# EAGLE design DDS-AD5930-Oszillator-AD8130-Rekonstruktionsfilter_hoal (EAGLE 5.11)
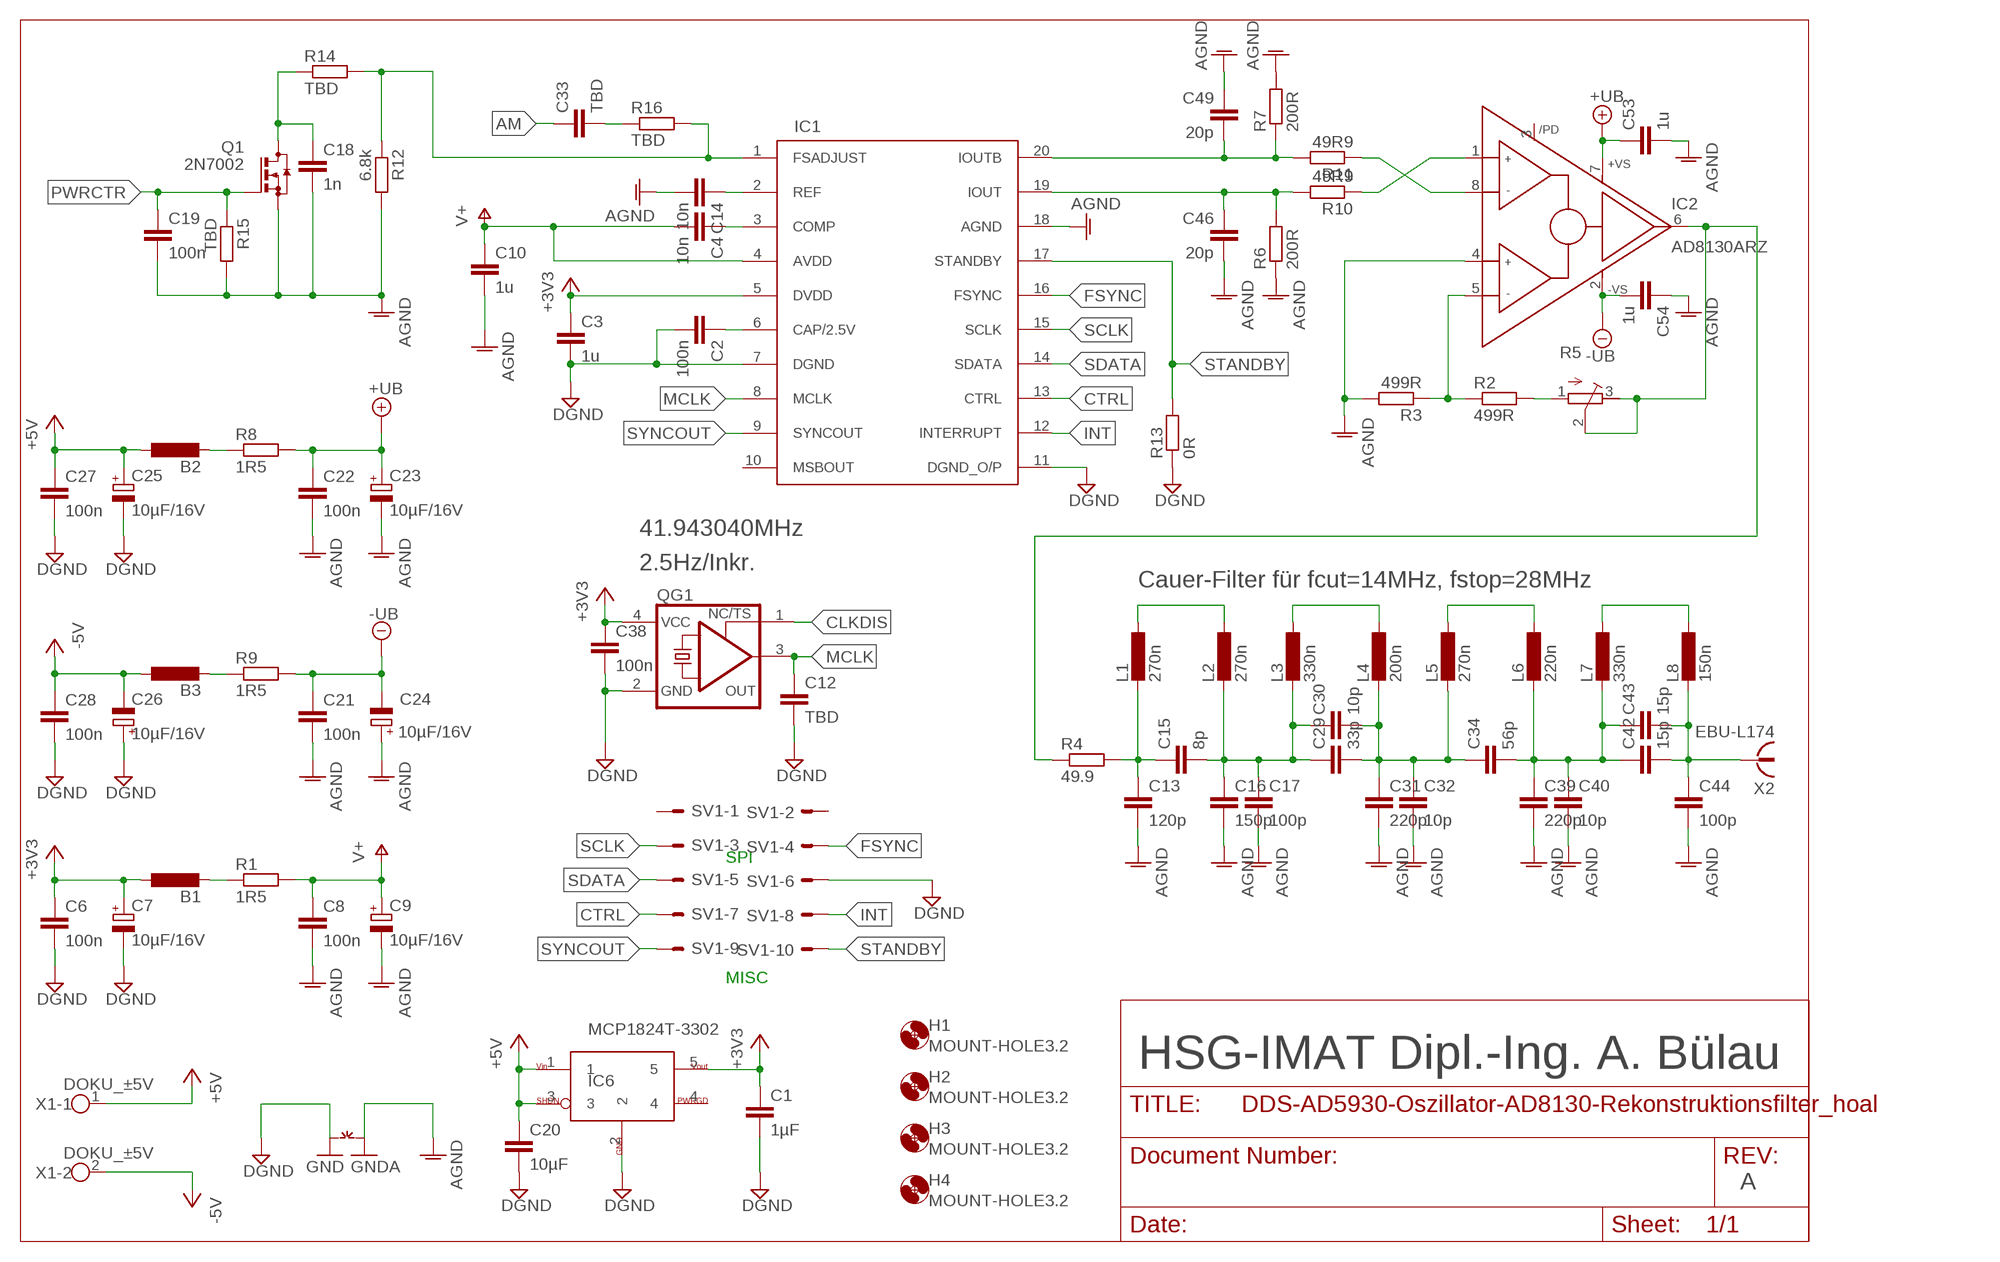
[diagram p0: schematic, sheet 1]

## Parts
B1  FERRITE-BEAD-SMD1206  [L1206]
B2  FERRITE-BEAD-SMD1206  [L1206]
B3  FERRITE-BEAD-SMD1206  [L1206]
C1  1µF  C-EUC0603  [C0603]
C2  100n  C-EUC0603  [C0603]
C3  1u  C-EUC0603  [C0603]
C4  10n  C-EUC0603  [C0603]
C6  100n  C-EUC0603  [C0603]
C7  10µF/16V  CPOL-EUSMCB  [SMC_B]
C8  100n  C-EUC0603  [C0603]
C9  10µF/16V  CPOL-EUSMCB  [SMC_B]
C10  1u  C-EUC0603  [C0603]
C12  TBD  C-EUC0603  [C0603]
C13  120p  C-EUC0805  [C0805]
C14  10n  C-EUC0603  [C0603]
C15  8p  C-EUC0805  [C0805]
C16  150p  C-EUC0805  [C0805]
C17  100p  C-EUC0805  [C0805]
C18  1n  C-EUC0603  [C0603]
C19  100n  C-EUC0603  [C0603]
C20  10µF  C-EUC1206  [C1206]
C21  100n  C-EUC0603  [C0603]
C22  100n  C-EUC0603  [C0603]
C23  10µF/16V  CPOL-EUSMCB  [SMC_B]
C24  10µF/16V  CPOL-EUSMCB  [SMC_B]
C25  10µF/16V  CPOL-EUSMCB  [SMC_B]
C26  10µF/16V  CPOL-EUSMCB  [SMC_B]
C27  100n  C-EUC0603  [C0603]
C28  100n  C-EUC0603  [C0603]
C29  33p  C-EUC0805  [C0805]
C30  10p  C-EUC0805  [C0805]
C31  220p  C-EUC0805  [C0805]
C32  10p  C-EUC0805  [C0805]
C33  TBD  C-EUC0603  [C0603]
C34  56p  C-EUC0805  [C0805]
C38  100n  C-EUC0603  [C0603]
C39  220p  C-EUC0805  [C0805]
C40  10p  C-EUC0805  [C0805]
C42  15p  C-EUC0805  [C0805]
C43  15p  C-EUC0805  [C0805]
C44  100p  C-EUC0805  [C0805]
C46  20p  C-EUC0603  [C0603]
C49  20p  C-EUC0603  [C0603]
C53  1u  C-EUC0603  [C0603]
C54  1u  C-EUC0603  [C0603]
H1  MOUNT-HOLE3.2  [3,2]
H2  MOUNT-HOLE3.2  [3,2]
H3  MOUNT-HOLE3.2  [3,2]
H4  MOUNT-HOLE3.2  [3,2]
IC1  AD5930  [TSSOP20]
IC2  AD8130ARZ  [SO8]
IC6  MCP1824T-3302  MCP1824T  [SOT23-5]
L1  270n  L-EUL1008  [L1008]
L2  270n  L-EUL1008  [L1008]
L3  330n  L-EUL1008  [L1008]
L4  200n  L-EUL1008  [L1008]
L5  270n  L-EUL1008  [L1008]
L6  220n  L-EUL1008  [L1008]
L7  330n  L-EUL1008  [L1008]
L8  150n  L-EUL1008  [L1008]
Q1  2N7002  BSS123  [SOT23]
QG1  XO-91  [91]
R1  1R5  R-EU_R0805  [R0805]
R2  499R  R-EU_R0603  [R0603]
R3  499R  R-EU_R0603  [R0603]
R4  49.9  R-EU_R0805  [R0805]
R5  R-TRIMM3314J  [RTRIM3314J]
R6  200R  R-EU_R0603  [R0603]
R7  200R  R-EU_R0603  [R0603]
R8  1R5  R-EU_R0805  [R0805]
R9  1R5  R-EU_R0805  [R0805]
R10  49R9  R-EU_R0603  [R0603]
R11  49R9  R-EU_R0603  [R0603]
R12  6.8k  R-EU_R0603  [R0603]
R13  0R  R-EU_R0603  [R0603]
R14  TBD  R-EU_R0603  [R0603]
R15  TBD  R-EU_R0603  [R0603]
R16  TBD  R-EU_R0603  [R0603]
SV1  ML10E  [ML10]
X1  DOKU_±5V  [DOKU_±5V]
X2  EBU-L174  [SMB_EBU-L174]
~NUDEV~1  GND-GNDAVIA  GND-GNDA  [GND-GNDA]

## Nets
+3V3: B1.1 C1.1 C3.1 C6.1 C7.+ C38.1 IC1.5(DVDD) IC6.5 QG1.4(VCC)
+5V: B2.1 C20.1 C25.+ C27.1 IC6.1 IC6.3 X1.1
+UB: C22.1 C23.+ C53.1 IC2.7(+VS) R8.2
-5V: B3.1 C26.- C28.2 X1.2
-UB: C21.2 C24.- C54.2 IC2.2(-VS) R9.2
AGND: C8.2 C9.- C10.2 C13.2 C14.2 C16.2 C17.2 C18.2 C19.2 C21.1 C22.2 C23.- C24.+ C31.2 C32.2 C39.2 C40.2 C44.2 C46.2 C49.2 C53.2 C54.1 IC1.18(AGND) IC2.4(REF) Q1.2(S) R3.2 R6.1 R7.2 R12.2 R15.2 ~NUDEV~1.GNDA
AM: C33.1
CLKDIS: QG1.1(TS)
CTRL: IC1.13(CTRL) SV1.7
DGND: C1.2 C2.2 C3.2 C6.2 C7.- C12.2 C20.2 C25.- C26.+ C27.2 C28.1 C38.2 IC1.7(DGND) IC1.11(DGND_O/P) IC6.2 QG1.2(GND) R13.1 SV1.6 ~NUDEV~1.GND
FSADJUST: IC1.1(FSADJUST) R12.1 R14.2 R16.2
FSYNC: IC1.16(FSYNC) SV1.4
INT: IC1.12(INTERRUPT) SV1.8
MCLK: C12.1 IC1.8(MCLK) QG1.3(OUT)
N$1: C13.1 C15.1 L1.2 R4.2
N$2: L1.1 L2.1
N$3: C15.2 C16.1 C17.1 C29.1 C30.1 L2.2 L3.2
N$4: C29.2 C30.2 C31.1 C32.1 C34.1 L4.2 L5.2
N$5: L3.1 L4.1
N$6: L5.1 L6.1
N$7: C33.2 R16.1
N$8: B1.2 R1.1
N$9: C2.1 IC1.6(CAP/2.5V)
N$12: C34.2 C39.1 C40.1 C42.1 C43.1 L6.2 L7.2
N$13: C4.1 IC1.3(COMP)
N$14: B2.2 R8.1
N$15: C49.1 IC1.20(IOUTB) R7.1 R11.2
N$16: L7.1 L8.1
N$17: C46.1 IC1.19(IOUT) R6.2 R10.2
N$18: B3.2 R9.1
N$19: IC2.1(IN+) R10.1
N$20: R2.2 R5.1(E)
N$22: IC2.8(IN-) R11.1
N$23: C18.1 Q1.3(D) R14.1
N$24: C14.1 IC1.2(REF)
N$26: IC2.5(FB) R2.1 R3.1
OUT: C42.2 C43.2 C44.1 L8.2 X2.1
PWRCTR: C19.1 Q1.1(G) R15.1
SCLK: IC1.15(SCLK) SV1.3
SDATA: IC1.14(SDATA) SV1.5
STANDBY: IC1.17(STANDBY) R13.2 SV1.10
SYNCOUT: IC1.9(SYNCOUT) SV1.9
V+: C4.2 C8.1 C9.+ C10.1 IC1.4(AVDD) R1.2
VRAW: IC2.6(OUT) R4.1 R5.2(S) R5.3(A)
Unconnected: IC1.10(MSBOUT) IC2.3(/PD) IC6.4 SV1.1 SV1.2

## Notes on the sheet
- 41.943040MHz
- 2.5Hz/Inkr.
- Cauer-Filter für fcut=14MHz, fstop=28MHz
- SPI
- MISC
- HSG-IMAT Dipl.-Ing. A. Bülau
- A

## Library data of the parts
B1-B3 = rcl:FERRITE-BEAD-SMD
C1-C4 C6 C8 C10 C12-C22 C27-C34 C38-C40 C42-C44 C46 C49 C53 C54 = rcl:C-EU: CAPACITOR, European symbol
C7 C9 C23-C26 = rcl:CPOL-EU: POLARIZED CAPACITOR, European symbol
H1-H4 = holes:MOUNT-HOLE: MOUNTING HOLE with drill center marker
IC1 = ad5930:AD5930
IC2 = AD8130:AD8130: Differential Receiver Amplifier
IC6 = MCP1824:MCP1824: 300mA, Low Voltage, Low Quiescent Current LDO Regulator
L1-L8 = rcl:L-EU: INDUCTOR, European symbol
Q1 = transistor-small-signal:BSS123: N-CHANNEL MOS FET
QG1 = crystal:XO-: CRYSTAL
R1-R4 R6-R16 = rcl:R-EU_: RESISTOR, European symbol
R5 = rcl:R-TRIMM: Trimm resistor
SV1 = con-ml:ML10E: HARTING
X1 = Spannungsdurchführung:DOKU_±5V
X2 = SMB-Reichelt:EBU-L174: Löt-Einbaubuchse
~NUDEV~1 = supply-dummy:GND-GNDA: Example of GND--GNDA NET-Connetor for more info read description in package

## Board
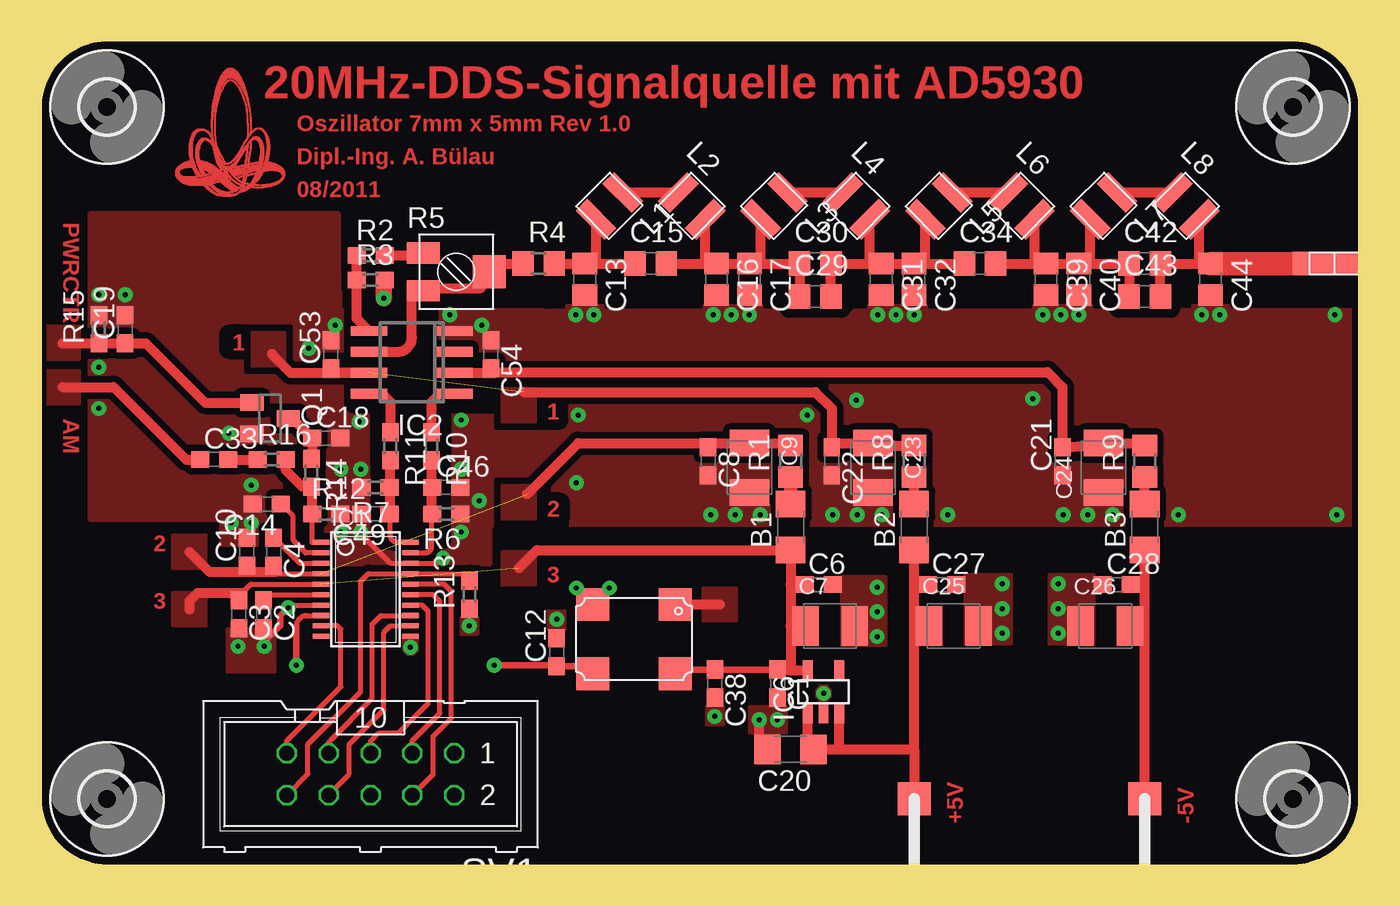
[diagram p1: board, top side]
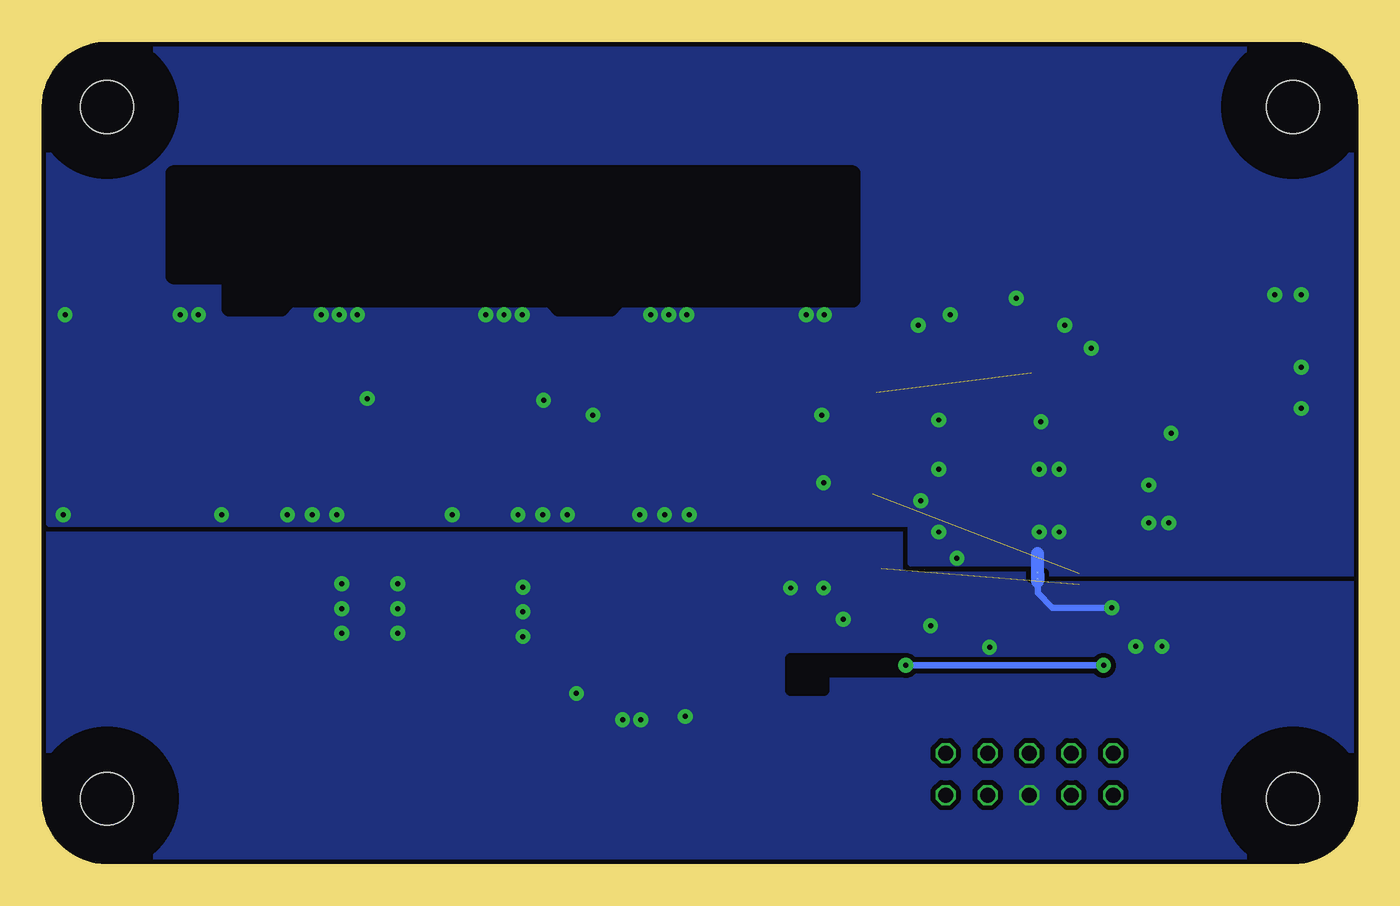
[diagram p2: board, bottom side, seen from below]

Size 80 x 50 mm. Coordinates in mm from the lower left corner, seen from the top.
Outline: 0,4 arc90 4,0 76,0 arc90 80,4 80,46 arc90 76,50 4,50 arc90 0,46 0,4
Copper layers (1*16): Top 0.035mm / dielectric 0.8mm / Bottom 0.035mm
Design rules "A. BÃ¼lau *": minimum track width 0.15mm, minimum drill 0.3mm, track to track 0.3mm, track to pad 0.15mm, pad to pad 0.15mm, via to via 0.15mm, smd to smd 0.15mm, copper to edge 0.3mm, drill to drill 0.3mm, minimum pad ring 0.15mm, minimum via ring 0.15mm, stop-mask expansion 0.3mm, vias tented up to drill 0.3mm, thermal gap 10mil
tRestrict: area 30.7,33.8 to 72,42; area 11.4,31.3 to 12.2,32.2; area 19,19.7 to 27.3,33.5; area 30.6,27 to 31.4,27.9; area 30.7,21.1 to 31.5,22; area 30.7,17.1 to 31.5,18
bRestrict: area 30.7,33.8 to 72,42; area 27.5,10.6 to 34.5,12.5
Milling: 8 lines

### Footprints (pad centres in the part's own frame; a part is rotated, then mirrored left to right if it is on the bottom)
L1206 = smd 1.6 x 1.8: 1 -1.4,0; 2 1.4,0
C0603 = smd 1.1 x 1: 1 -0.85,0; 2 0.85,0
SMC_B = smd 1.6 x 2.4: + -1.5,0; - 1.5,0
C0805 = smd 1.3 x 1.5: 1 -0.95,0; 2 0.95,0
C1206 = smd 1.6 x 1.8: 1 -1.4,0; 2 1.4,0
3,2 = hole 3.2: 0,0
TSSOP20 = smd 0.305 x 0.991: 1 -3.175,-2.718; 2 -2.54,-2.718; 3 -1.905,-2.718; 4 -1.27,-2.718; 5 -0.635,-2.718; 6 0,-2.718; 7 0.635,-2.718; 8 1.27,-2.718; 9 1.905,-2.718; 10 2.54,-2.718; 11 2.54,2.718; 12 1.905,2.718; 13 1.27,2.718; 14 0.635,2.718; 15 0,2.718; 16 -0.635,2.718; 17 -1.27,2.718; 18 -1.905,2.718; 19 -2.54,2.718; 20 -3.175,2.718
SO8 = smd 0.6 x 2.2: 1 -1.905,-2.6; 2 -0.635,-2.6; 3 0.635,-2.6; 4 1.905,-2.6; 5 1.905,2.6; 6 0.635,2.6; 7 -0.635,2.6; 8 -1.905,2.6
SOT23-5 = smd 0.6 x 1.2: 1 -0.95,-1.306; 2 0,-1.306; 3 0.95,-1.306; 4 0.95,1.306; 5 -0.95,1.306
L1008 = smd 1 x 2.5: 1 -1.15,0; 2 1.15,0
SOT23 = smd 1 x 1.4: 1 -0.95,-1.1; 2 0.95,-1.1; 3 0,1.1
91 = smd 2 x 2: 1 -2.5,-2.1; 2 2.5,-2.1; 3 2.5,2.1; 4 -2.5,2.1
R0805 = smd 1.3 x 1.5: 1 -0.95,0; 2 0.95,0
R0603 = smd 1.1 x 1: 1 -0.85,0; 2 0.85,0
RTRIM3314J = smd 1.3 x 2: 1 -1.15,-2; 3 1.15,-2 | smd 2 x 2: 2 0,2
ML10 = drill 0.914 octagon: 1 -5.08,-1.27; 2 -5.08,1.27; 3 -2.54,-1.27; 4 -2.54,1.27; 5 0,-1.27; 6 0,1.27; 7 2.54,-1.27; 8 2.54,1.27; 9 5.08,-1.27; 10 5.08,1.27
DOKU_±5V = smd 2 x 2: 1 0,-7; 2 0,7
SMB_EBU-L174 = smd 4 x 1.44: 1 -2,0
GND-GNDA = smd 0.1 x 0.1: GND 0.25,0; GNDA -0.15,0

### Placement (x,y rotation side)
B1  45.5,20.5 90 top
B2  53,20.5 90 top
B3  67,20.5 90 top
C1  44.7,11 270 top
C2  13.5,15.2 270 top
C3  12,15.2 270 top
C4  14.1,19 270 top
C6  47.2,17 0 top
C7  47.9,14.5 0 top
C8  40.5,24.5 270 top
C9  43,24.1 270 top
C10  12.5,19 90 top
C12  31.3,12.9 90 top
C13  33,35.55 270 top
C14  13.7,21.9 180 top
C15  37,36.5 0 top
C16  41,35.55 270 top
C17  43,35.55 270 top
C18  17.3,25.9 0 top
C19  5.1,32.5 90 top
C20  45.5,7 180 top
C21  62,24.5 90 top
C22  48,24.5 270 top
C23  50.5,24.1 270 top
C24  64.5,24.1 90 top
C25  55.4,14.5 0 top
C26  64.6,14.5 0 top
C27  54.7,17 0 top
C28  65.3,17 0 top
C29  47,34.5 0 top
C30  47,36.5 0 top
C31  51,35.55 270 top
C32  53,35.55 270 top
C33  10.5,24.6 0 top
C34  57,36.5 0 top
C38  40.9,11 270 top
C39  61,35.55 270 top
C40  63,35.55 270 top
C42  67,36.5 0 top
C43  67,34.5 0 top
C44  71,35.55 270 top
C46  24.6,22.9 0 top
C49  20.3,21.3 180 top
C53  17.6,31 90 top
C54  27.3,31 270 top
H1  4,4 90 top
H2  4,46 90 top
H3  76,46 90 top
H4  76,4 90 top
IC1  19.7,16.4 270 top
IC2  22.5,30.5 90 top
IC6  47.5,10.5 0 top
L1  34.5,40 225 top
L2  39.5,40 315 top
L3  44.5,40 225 top
L4  49.5,40 315 top
L5  54.5,40 225 top
L6  59.5,40 315 top
L7  64.5,40 225 top
L8  69.5,40 315 top
Q1  13.9,27.1 270 top
QG1  36,13.7 180 top
R1  45.5,24.5 90 top
R2  20,37 0 top
R3  20,35.5 0 top
R4  30.2,36.5 0 top
R5  25.2,36 270 top
R6  24.6,21.3 180 top
R7  20.3,22.9 180 top
R8  53,24.5 90 top
R9  67,24.5 90 top
R10  23.7,25.4 270 top
R11  21.2,25.4 270 top
R12  17.3,21.3 0 top
R13  26,16.4 90 top
R14  16.4,23.8 270 top
R15  3.5,32.5 90 top
R16  14,24.6 0 top
SV1  20,5.5 180 top
U$1  [LOGO]  8,40.5 0 top
X1  60,4 270 top
X2  80,36.5 0 top
~NUDEV~1  19.5,17.6 270 bottom

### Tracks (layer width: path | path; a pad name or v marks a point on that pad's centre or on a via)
+3V3  (1 unrouted)
  Top 0.305: IC1.5 12.73,17.04 12.2,16.5
  Top 0.406: C1.1 C38.1 38.5,11.85 QG1.4
  Top 0.61: 45.5,17 45.5,14.5 | 45.5,17 B1.1 30.1,19.1 29,18 | 45.5,11.81 IC6.5 | 45.5,14.5 45.5,11.81 | 45.5,14.5 C7.+ | 45.5,17 C6.1 | 45.5,11.81 44.7,11.81 C1.1 | 11.55,16.5 C3.1 | 11.55,16.5 9.5,16.5 9,16 9,15.5 | 11.55,16.5 12.2,16.5
  Top 0.813: C7.+ 46.4,14.45
  pour Top (no thermals): 28,19 30,19 30,17 28,17
  pour Top (no thermals): 8,16.5 10,16.5 10,14.5 8,14.5
+5V
  Top 0.406: C20.1 46.56,7.46
  Top 0.61: 53,14.5 53,17 | 53,17 B2.1 | 53,14.5 C25.+ | 53,17 C27.1 | IC6.1 46.55,7.5 C20.1 48.45,7 | 48.45,7 IC6.3 | 53,7 X1.1 | 53,7 53,14.5 | 48.45,7 53,7
+UB  (1 unrouted)
  Top 0.61: 29.3,28.7 47,28.7 48,27.7 C22.1 48.25,25.6 C23.+ 50.65,25.45 R8.2 53,25.6 | C53.1 17.89,29.86 IC2.7 15.13,29.86 14,31
  pour Top (no thermals): 28,28.9 30,28.9 30,26.9 28,26.9
  pour Top (no thermals): 12.8,30.3 12.8,32.3 14.8,32.3 14.8,30.3
-5V
  Top 0.61: 67,14.5 67,17 | 67,17 B3.1 | 67,17 C28.2 | 67,14.5 C26.- | X1.2 67,14.5
-UB
  Top 0.61: C21.2 65.5,25.5 | R9.2 67,25.6 C24.- 65.5,25.6 C21.2 | IC2.2 27.57,29.86 27.6,29.9 | C54.2 27.3,30.2 27.6,29.9 | 27.6,29.9 61.1,29.9 62,29 C21.2
AGND  (via drill 0.3 pad 0.9)
  Top 0.305: v24.4,18.6 24.11,18.3 IC1.18 21.2,18.3 19.5,20
  Top 1.016: v20.8,34.4 20.8,35.45 R3.2
  Bottom 0.8: ~NUDEV~1.GNDA 19.5,18.9
  other vias: 60.8,33.4 61.9,33.4 63,33.4 40.8,33.4 41.9,33.4 43,33.4 50.8,33.4 51.9,33.4 53,33.4 32.45,33.4 33.55,33.4 48.05,21.25 49.55,21.25 51.05,21.25 12.75,20.75 11.55,20.75 12.75,23.05 24.8,33.4 70.45,33.4 71.55,33.4 18.2,24 19.4,24 18.2,20.2 19.4,20.2 17.85,32.75 16.25,31.35 40.65,21.25 42.15,21.25 43.65,21.25 25.5,24 25.5,20.2 26.6,22.1 19.3,26.9 3.5,34.6 5.1,34.6 11.4,26.2 32.5,23.2 32.6,27.3 46.5,27.3 25.5,27 78.65,21.25 78.55,33.4 3.5,30.2 3.5,27.7 60.2,28.3 49.5,28.2 55.05,21.25 62.05,21.25 63.55,21.25 65.05,21.25 69.05,21.25 26.75,32.75
  pour Bottom (isolate 0.3, rank 2, no thermals): 0,50 80,50 79.5,20.7 27.2,20.7 27.2,18.3 19.2,18.3 19.2,17.7 0,17.7
  pour Top (no thermals): 60.26,33.95 63.75,33.95 63.75,32.86 60.26,32.86
  pour Top (no thermals): 40.26,33.95 43.75,33.95 43.75,32.86 40.26,32.86
  pour Top (no thermals): 50.26,33.95 53.75,33.95 53.75,32.87 50.26,32.86
  pour Top (no thermals): 31.91,33.95 34.09,33.95 34.09,32.86 31.91,32.86
  pour Top (no thermals): 47.41,23.1 49.2,23.1 49.2,21.8 51.59,21.8 51.59,20.71 47.41,20.71
  pour Top (no thermals): 69.91,33.95 72.09,33.95 72.09,32.86 69.91,32.86
  pour Top (isolate 0.3, no thermals): 17.7,23.4 17.7,24.2 18,24.5 19.6,24.5 19.9,24.2 19.9,20 19.6,19.7 18,19.7 17.7,20
  pour Top (no thermals): 40.01,23.1 41.8,23.1 41.8,21.8 44.19,21.8 44.19,20.71 40.01,20.71
  pour Top (isolate 0.3, no thermals): 25,19.9 25,24.3 25.2,24.5 26,22.7 26.1,22.6 26.9,22.6 27.1,22.4 27.1,21.8 26.9,21.6 26.1,21.6 26,21.5 26,19.9 25.8,19.7 25.2,19.7
  pour Top (isolate 0.3, no thermals): 19.8,25.4 18.7,25.4 18.7,26.4 19.8,26.4
  pour Top (no thermals): 3,33.9 3,35.2 5.6,35.2 5.6,33.9
  pour Top (no thermals): 12.1,26.7 12.1,25.6 10.8,25.6 10.8,26.7
  pour Top (isolate 0.4, rank 2, no thermals): 3,39.5 18,39.5 18,35.8 18.1,35.8 18.1,33.6 79.5,33.6 79.5,20.7 27.2,20.7 27.2,18.3 17.5,18.3 17.5,19.5 11,19.5 11,21 3,21
  pour Top (no thermals): 61.41,23.1 63.2,23.1 63.2,21.8 65.59,21.8 65.59,20.71 61.41,20.71
AM
  Top 0.61: 1.3,29 4.4,29 8.8,24.6 C33.1
  pour Top (no thermals): 0.3,28 0.3,30 2.3,30 2.3,28
CLKDIS
  Top 0.61: QG1.1 41.2,15.8
  pour Top (no thermals): 40.2,16.8 42.2,16.8 42.2,14.8 40.2,14.8
CTRL
  Top 0.305: IC1.13 20.63,15.13 20.1,14.6 20.1,10.1 17.6,7.6 17.46,7.46 SV1.7
DGND  (via drill 0.3 pad 0.9)
  Top 0.2: v32.5,16.8 QG1.2 | v34.5,16.8 34.3,16.8 33.5,16
  Top 0.305: IC1.7 15.16,15.77 v15,15.6
  Top 0.406: 15.16,15.77 14.5,15.1 14.5,14.5 13.5,13.5 13.5,13
  Top 0.61: v43.6,8.8 43.6,7.5 C20.2
  Bottom 0.4: v15,15.6 18.6,15.6 19.5,16.5 ~NUDEV~1.GND
  Bottom 0.8: ~NUDEV~1.GND 19.5,17.2
  other vias: 61.75,17.05 61.75,15.55 61.75,14.05 58.35,14.05 58.35,15.55 58.35,17.05 50.75,13.85 50.75,15.35 50.75,16.85 44.7,8.8 11.95,13.25 13.55,13.25 22.42,13.21 26,14.5 47.5,10.4 31.3,14.9 40.9,9
  pour Bottom (isolate 0.3, rank 4, no thermals): 0,17.6 27.6,17.6 27.6,20.3 80,20.3 80,0 0,0
  pour Top (no thermals): 63.9,17.59 63.9,13.41 61.21,13.41 61.21,17.59
  pour Top (no thermals): 56.09,17.59 58.89,17.59 58.89,13.41 56.09,13.41
  pour Top (no thermals): 48.6,13.31 48.6,17.49 51.29,17.49 51.29,13.31
  pour Top (no thermals): 11.3,11.7 11.3,14.3 14.19,14.3 14.19,11.71
  pour Top (isolate 0.3, no thermals): 25.5,15 26.5,15 26.5,14 25.5,14
  pour Top (isolate 0.3, no thermals): 47.8,9.79 47.8,10 48,10.2 48,10.6 47.8,10.8 47.8,10.9 47.2,10.9 47.2,10.8 47,10.6 47,10.2 47.2,10 47.2,9.79
  pour Top (isolate 0.3, no thermals): 21.92,13.71 21.92,13.01 22.22,12.71 22.62,12.71 22.92,13.01 22.92,13.71
  pour Top (no thermals): 45.24,9.6 45.24,8 43.01,8 43.01,9.6
  pour Top (no thermals): 30.8,14.3 30.8,15.4 31.8,15.4 31.8,14.3
  pour Top (no thermals): 41.4,9.6 41.4,8.5 40.4,8.5 40.4,9.6
FSADJUST
  Top 0.305: R12.1 16.45,19.57 IC1.1
  Top 0.61: R12.1 16.45,22.95 R14.2 15.85,22.95 14.85,23.95 R16.2
FSYNC
  Top 0.305: IC1.16 24.46,17.04 24.9,16.6 24.9,8.9 23.8,7.8 23.8,5.49 SV1.4
INT
  Top 0.305: SV1.8 17.46,4.26 18.7,5.5 18.7,7.3 20.8,9.4 20.8,14.1 21.2,14.49 IC1.12
MCLK  (via drill 0.3 pad 0.9)
  Top 0.305: IC1.8 16.13,15.13 arc90 15.5,14.5
  Top 0.406: v15.5,12.1 15.5,14.5 | v27.5,12.1 31.25,12.1 31.25,12.05 C12.1 33.5,12.05 QG1.3
  Bottom 0.406: v15.5,12.1 v27.5,12.1
N$1
  Top 0.61: R4.2 C13.1 33.69,36.5 | 33.69,36.5 L1.2 | 33.69,36.5 C15.1
N$2
  Top 0.61: L1.1 L2.1
N$3
  Top 0.61: C29.1 C30.1 43.69,36.5 | 40.31,36.5 L2.2 | C15.2 40.31,36.5 | 43.69,36.5 L3.2 | 40.31,36.5 C16.1 C17.1 43.69,36.5
N$4
  Top 0.61: C29.2 C30.2 50.31,36.5 50.31,36.6 | 50.31,36.6 L4.2 | 53.69,36.6 53.69,36.5 C34.1 | 53.69,36.6 L5.2 | 53.69,36.6 53,36.6 C32.1 C31.1 51,36.6 50.31,36.6
N$5
  Top 0.61: L3.1 L4.1
N$6
  Top 0.61: L5.1 L6.1
N$7
  Top 0.61: C33.2 R16.1
N$8
  Top 0.813: B1.2 R1.1
N$9
  Top 0.305: IC1.6 13.5,16.4 C2.1
N$12
  Top 0.61: C43.1 C42.1 63.69,36.5 | 60.31,36.5 L6.2 | C34.2 60.31,36.5 | 60.31,36.5 C39.1 C40.1 63.69,36.5 | 63.69,36.5 L7.2
N$13
  Top 0.305: IC1.3 15.7,18.3 14.5,19.5 14.45,19.5 C4.1
N$14
  Top 0.61: B2.2 R8.1
N$15
  Top 0.305: IC1.20 21.62,19.57 arc-90 21.2,20 21.2,21.3
  Top 0.406: 21.2,21.3 C49.1
  Top 0.61: 21.2,22.9 R11.2 | 21.2,22.9 R7.1 | 21.2,21.3 21.2,22.9
N$16
  Top 0.61: L7.1 L8.1
N$17
  Top 0.305: IC1.19 23.34,18.94 arc90 23.7,19.3 23.7,21.3
  Top 0.406: 23.7,21.3 R6.2
  Top 0.61: 23.7,22.9 R10.2 | 23.7,22.9 C46.1 | 23.7,21.3 23.7,22.9
N$18
  Top 0.61: B3.2 R9.1
N$19
  Top 0.61: IC2.1 24.2,28.59 23.7,28.1 R10.1
N$20
  Top 0.61: R2.2 23.2,37 R5.1
N$22
  Top 0.61: IC2.8 20.7,28.59 21.2,28.1 R11.1
N$23
  Top 0.61: R14.1 16.45,24.65 C18.1 15.25,27.1 Q1.3
N$24
  Top 0.305: IC1.2 16.06,18.94 15.3,19.7 15.3,21.15 C14.1
N$26
  Top 0.61: R2.1 R3.1 19.15,33.16 IC2.5
OUT
  Top 0.61: C43.2 C42.2 70.31,36.5 | 70.31,36.5 L8.2 | 70.31,36.5 C44.1
  Top 1.42: C44.1 X2.1
PWRCTR
  Top 0.61: 1.3,31.65 R15.1 C19.1 6.35,31.65 9.95,28.05 Q1.1
  pour Top (no thermals): 2.3,32.7 2.3,30.7 0.3,30.7 0.3,32.7
SCLK
  Top 0.305: IC1.15 23.8,16.4 24.2,16 24.2,9.2 22.54,7.54 SV1.3
SDATA
  Top 0.305: IC1.14 23.14,15.77 23.5,15.4 23.5,9.8 21.7,8 20.5,8 20,7.5 SV1.5
STANDBY
  Top 0.305: SV1.10 16.2,5.5 16.2,7.3 19.4,10.5 19.4,15.4 19.4,15.9 19.4,17.2 19.87,17.67 IC1.17 26,17.67 R13.2
SYNCOUT
  Top 0.305: IC1.9 18,14.49 18.2,14.3 18.2,10.8 14.92,7.52 SV1.9
V+  (1 unrouted)
  Top 0.305: 14.3,17.8 14.43,17.67 IC1.4 | C4.2 14,18.05 14,17.8
  Top 0.61: R1.2 45.5,25.6 C9.+ 40.5,25.6 | 12.5,17.8 C10.1 | 12.5,17.8 10.2,17.8 9,19 | 40.5,25.6 C8.1 | 12.5,17.8 14,17.8 14.3,17.8 | 40.5,25.6 32.6,25.6 29.5,22.5
  pour Top (no thermals): 8,20 10,20 10,18 8,18
  pour Top (no thermals): 28,23 30,23 30,21 28,21
VRAW
  Top 0.61: R4.1 27.2,36.5 R5.2 26.7,35 23.7,35 R5.3 22.5,34.85 22.5,32 arc-90 21.64,31.14 IC2.6

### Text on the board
Top: 20MHz-DDS-Signalquelle mit AD5930 | Oszillator 7mm x 5mm Rev 1.0 | Dipl.-Ing. A. Bülau | 08/2011 | PWRCTR | 1 | AM | 1 | 2 | 2 | 3 | 3 | +5V | -5V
